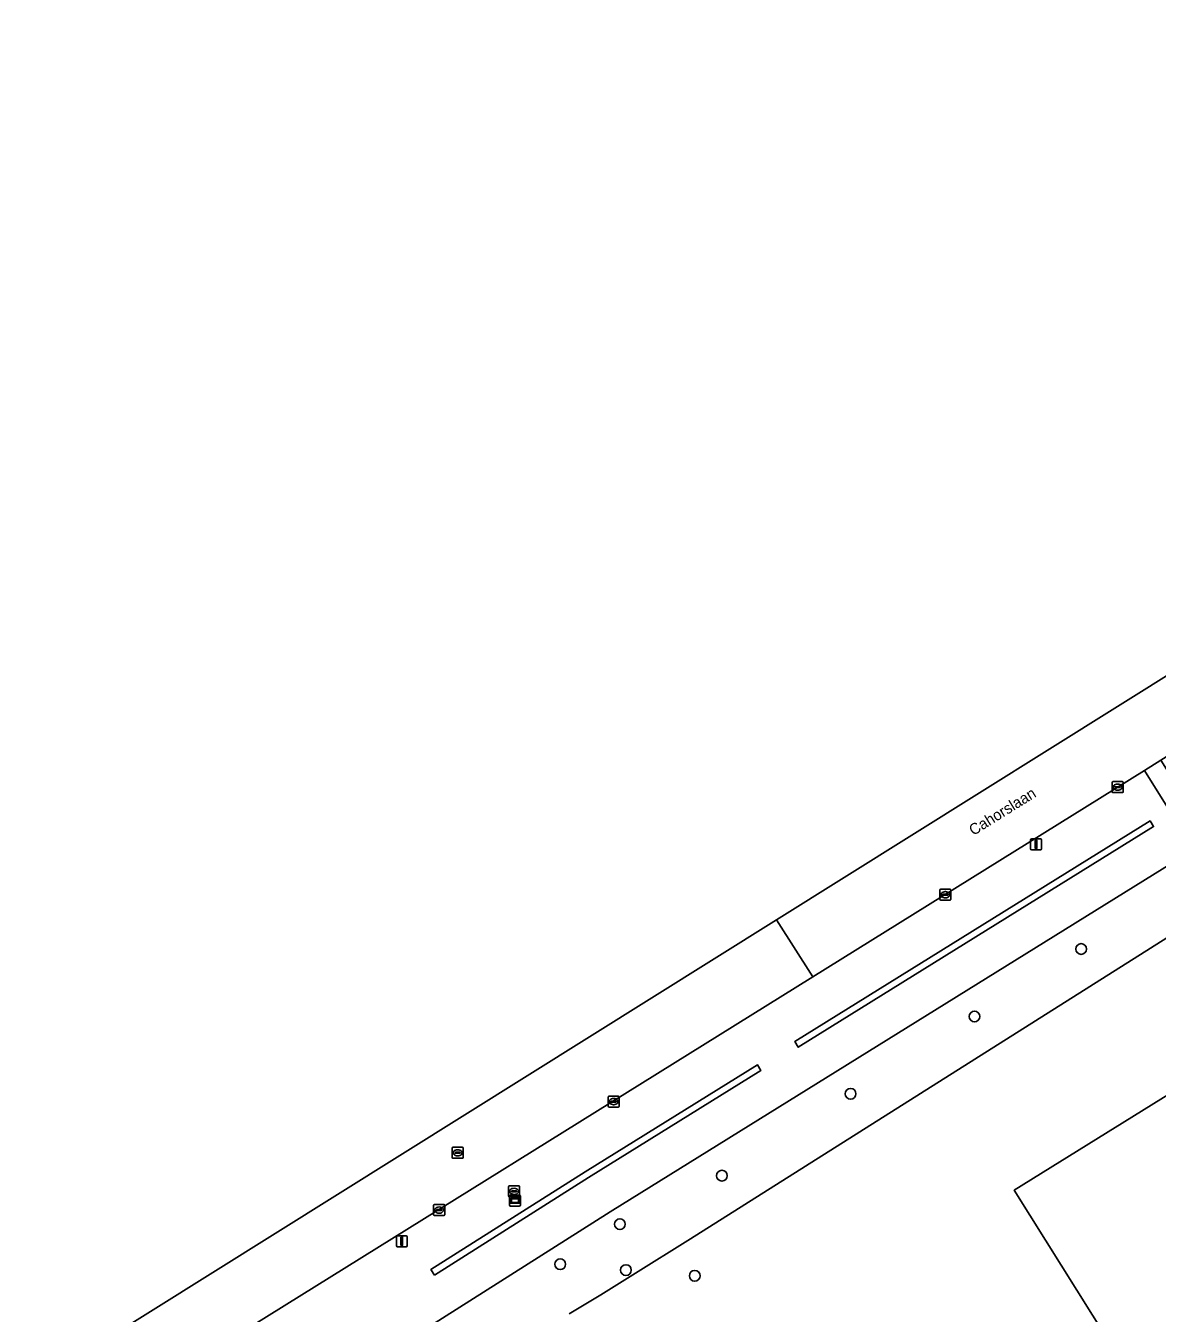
# Model space of a CAD drawing. Extents: x 158455 to 159797, y 387218 to 388672.
# Drawn here: x 158483.6 to 158586.4, y 387894.7 to 388011.6 of the extents above; entities that cross this region are included whole.
import ezdxf

# ---------------------------------------------------------------- set-up
doc = ezdxf.new("R2010")
doc.units = 0
for name, color, linetype in [('IMGEO_Boom', 7, 'Continuous'), ('IMGEO_Brandkraan', 7, 'Continuous'), ('IMGEO_Erf', 7, 'Continuous'), ('IMGEO_Groenvoorziening', 7, 'Continuous'), ('IMGEO_Haag', 7, 'Continuous'), ('IMGEO_Kolk', 7, 'Continuous'), ('IMGEO_Lichtmast', 7, 'Continuous'), ('IMGEO_Openbare_ruimte_label', 7, 'Continuous'), ('IMGEO_Pand', 7, 'Continuous'), ('IMGEO_Rijbaan_lokaal_gesloten', 7, 'Continuous'), ('IMGEO_Rijbaan_lokaal_open', 7, 'Continuous'), ('IMGEO_Rioolput', 7, 'Continuous'), ('IMGEO_Verklikker', 7, 'Continuous'), ('IMGEO_Voetpad_open', 7, 'Continuous')]:
    doc.layers.add(name, color=color, linetype=linetype)

msp = doc.modelspace()

# ---------------------------------------------------------------- linework, layer by layer
at = {"layer": 'IMGEO_Boom'}
for centre in [(158579.46, 387927.76), (158569.77, 387921.63), (158558.51, 387914.61), (158546.82, 387907.17), (158537.55, 387902.77), (158532.13, 387899.13), (158538.1, 387898.6), (158544.35, 387898.08)]:
    msp.add_circle(centre, 0.489, dxfattribs=at)
at = {"layer": 'IMGEO_Brandkraan'}
for p, q in [((158527.44, 387905.32), (158527.44, 387906.18)), ((158527.51, 387906.25), (158528.36, 387906.25)), ((158528.36, 387905.25), (158527.51, 387905.25)), ((158527.7, 387905.74), (158527.7, 387905.76)), ((158527.74, 387905.79), (158528.14, 387905.79)), ((158528.13, 387905.71), (158527.74, 387905.71)), ((158527.95, 387905.47), (158527.92, 387905.47)), ((158527.93, 387906.03), (158527.95, 387906.03)), ((158528.18, 387905.76), (158528.18, 387905.74)), ((158528.44, 387906.18), (158528.44, 387905.32))]:
    msp.add_line(p, q, dxfattribs=at)
for points in [[(158527.44, 387905.32), (158527.44, 387906.18)], [(158527.51, 387906.25), (158528.36, 387906.25)], [(158528.36, 387905.25), (158527.51, 387905.25)], [(158528.44, 387906.18), (158528.44, 387905.32)]]:
    msp.add_lwpolyline(points, dxfattribs=at)
for centre, radius, start, end in [((158527.51, 387906.18), 0.0765, 91.552, 178.448), ((158527.51, 387906.18), 0.0765, 91.552, 178.448), ((158527.51, 387905.33), 0.0765, 181.552, 268.448), ((158527.51, 387905.33), 0.0765, 181.552, 268.448), ((158527.74, 387905.75), 0.0403, 85.8775, 175.7526), ((158527.73, 387905.74), 0.0366, 178.938, 274.7102), ((158528.14, 387905.75), 0.043, 264.8664, 352.4533), ((158528.14, 387905.76), 0.0386, 1.7309, 96.639), ((158528.36, 387906.18), 0.0765, 1.552, 88.448), ((158528.36, 387906.18), 0.0765, 1.552, 88.448), ((158528.36, 387905.33), 0.0765, 271.552, 358.448), ((158528.36, 387905.33), 0.0765, 271.552, 358.448)]:
    msp.add_arc(centre, radius, start, end, dxfattribs=at)
for centre, major_axis, ratio, start_param, end_param in [((158527.92, 387905.75), (-0.387, 0.002), 0.722429, 4.712389, 7.853982), ((158527.95, 387905.75), (-0.39, 0.002), 0.717154, 1.570796, 4.712389)]:
    msp.add_ellipse(centre, major_axis=major_axis, ratio=ratio, start_param=start_param, end_param=end_param, dxfattribs=at)
at = {"layer": 'IMGEO_Erf'}
for points in [[(158573.38, 387905.85), (158595.86, 387919.82), (158595.79, 387919.92), (158598.08, 387921.36), (158594.51, 387926.76), (158593.7, 387926.26), (158592.36, 387928.36), (158590.22, 387926.79), (158588.61, 387928.98), (158590.79, 387930.57), (158590.71, 387930.96), (158543.97, 387901.44), (158538.73, 387898.18), (158535.83, 387896.34), (158532.94, 387894.61)], [(158570.32, 387880.74), (158572.79, 387877.35), (158575.89, 387872.44), (158584.05, 387859.54), (158587.13, 387854.66), (158588.43, 387852.56), (158594.08, 387856.34), (158584.31, 387871.94), (158591.71, 387876.58), (158573.38, 387905.85)]]:
    msp.add_lwpolyline(points, dxfattribs=at)
at = {"layer": 'IMGEO_Groenvoorziening'}
for points in [[(158488.57, 387883.89), (158493.31, 387876.39), (158500, 387880.63), (158536.68, 387903.89), (158589.7, 387936.8), (158585.21, 387943.98), (158555.08, 387925.23), (158500, 387890.96)], [(158553.75, 387918.84), (158553.44, 387919.35), (158585.72, 387939.39), (158586.04, 387938.88)], [(158585.72, 387939.39), (158553.44, 387919.35), (158553.75, 387918.84), (158586.04, 387938.88)], [(158520.7, 387898.14), (158520.38, 387898.65), (158534.4, 387907.53), (158550.04, 387917.24), (158550.36, 387916.73), (158534.71, 387907.02)], [(158520.7, 387898.14), (158534.71, 387907.02), (158550.36, 387916.73), (158550.04, 387917.24), (158534.4, 387907.53), (158520.38, 387898.65)]]:
    msp.add_lwpolyline(points, close=True, dxfattribs=at)
msp.add_lwpolyline([(158532.94, 387894.61), (158535.83, 387896.34), (158538.73, 387898.18), (158543.97, 387901.44), (158590.71, 387930.96), (158590.79, 387930.57), (158592.36, 387928.36), (158593.7, 387926.26), (158594.51, 387926.76), (158598.08, 387921.36), (158598.23, 387921.11), (158599.1, 387921.66), (158592.42, 387932.28), (158589.7, 387936.8), (158536.68, 387903.89), (158500, 387880.63)], dxfattribs=at)
at = {"layer": 'IMGEO_Haag'}
for points in [[(158585.72, 387939.39), (158553.44, 387919.35), (158553.75, 387918.84), (158586.04, 387938.88)], [(158520.7, 387898.14), (158534.71, 387907.02), (158550.36, 387916.73), (158550.04, 387917.24), (158534.4, 387907.53), (158520.38, 387898.65)]]:
    msp.add_lwpolyline(points, close=True, dxfattribs=at)
at = {"layer": 'IMGEO_Kolk'}
for p, q in [((158582.27, 387942.03), (158582.27, 387942.89)), ((158582.35, 387942.96), (158583.2, 387942.96)), ((158582.76, 387942.74), (158582.79, 387942.74)), ((158583.27, 387942.89), (158583.27, 387942.03)), ((158583.2, 387941.96), (158582.35, 387941.96)), ((158582.53, 387942.45), (158582.53, 387942.47)), ((158582.57, 387942.5), (158582.97, 387942.5)), ((158582.97, 387942.42), (158582.57, 387942.42)), ((158582.78, 387942.18), (158582.76, 387942.18)), ((158583.02, 387942.47), (158583.02, 387942.45)), ((158566.61, 387932.27), (158566.61, 387933.12)), ((158566.68, 387933.19), (158567.54, 387933.19)), ((158567.54, 387932.19), (158566.68, 387932.19)), ((158566.87, 387932.69), (158566.87, 387932.7)), ((158566.91, 387932.74), (158567.31, 387932.74)), ((158567.31, 387932.65), (158566.91, 387932.65)), ((158567.12, 387932.41), (158567.09, 387932.41)), ((158567.1, 387932.97), (158567.12, 387932.97)), ((158567.35, 387932.7), (158567.35, 387932.69)), ((158567.61, 387933.12), (158567.61, 387932.27)), ((158536.49, 387913.47), (158536.49, 387914.33)), ((158536.56, 387914.4), (158537.42, 387914.4)), ((158537.42, 387913.4), (158536.56, 387913.4)), ((158536.75, 387913.89), (158536.75, 387913.91)), ((158536.79, 387913.94), (158537.19, 387913.94)), ((158537.19, 387913.86), (158536.79, 387913.86)), ((158537, 387913.62), (158536.97, 387913.62)), ((158536.98, 387914.18), (158537, 387914.18)), ((158537.23, 387913.91), (158537.23, 387913.89)), ((158537.49, 387914.33), (158537.49, 387913.47)), ((158520.63, 387903.63), (158520.63, 387904.48)), ((158520.71, 387904.56), (158521.56, 387904.56)), ((158520.89, 387904.05), (158520.89, 387904.06)), ((158520.93, 387904.1), (158521.33, 387904.1)), ((158521.12, 387904.33), (158521.14, 387904.33)), ((158521.37, 387904.06), (158521.37, 387904.05)), ((158521.63, 387904.48), (158521.63, 387903.63)), ((158521.56, 387903.55), (158520.71, 387903.55)), ((158521.33, 387904.01), (158520.93, 387904.01)), ((158521.14, 387903.78), (158521.12, 387903.78))]:
    msp.add_line(p, q, dxfattribs=at)
for points in [[(158582.27, 387942.03), (158582.27, 387942.89)], [(158582.35, 387942.96), (158583.2, 387942.96)], [(158583.27, 387942.89), (158583.27, 387942.03)], [(158583.2, 387941.96), (158582.35, 387941.96)], [(158566.61, 387932.27), (158566.61, 387933.12)], [(158566.68, 387933.19), (158567.54, 387933.19)], [(158567.54, 387932.19), (158566.68, 387932.19)], [(158567.61, 387933.12), (158567.61, 387932.27)], [(158536.49, 387913.47), (158536.49, 387914.33)], [(158536.56, 387914.4), (158537.42, 387914.4)], [(158537.42, 387913.4), (158536.56, 387913.4)], [(158537.49, 387914.33), (158537.49, 387913.47)], [(158520.63, 387903.63), (158520.63, 387904.48)], [(158520.71, 387904.56), (158521.56, 387904.56)], [(158521.63, 387904.48), (158521.63, 387903.63)], [(158521.56, 387903.55), (158520.71, 387903.55)]]:
    msp.add_lwpolyline(points, dxfattribs=at)
for centre, radius, start, end in [((158582.35, 387942.88), 0.0765, 91.552, 178.448), ((158582.35, 387942.88), 0.0765, 91.552, 178.448), ((158583.2, 387942.88), 0.0765, 1.552, 88.448), ((158583.2, 387942.88), 0.0765, 1.552, 88.448), ((158582.35, 387942.04), 0.0765, 181.552, 268.448), ((158582.35, 387942.04), 0.0765, 181.552, 268.448), ((158582.57, 387942.46), 0.0403, 85.8775, 175.7526), ((158582.57, 387942.45), 0.0366, 178.938, 274.7102), ((158582.98, 387942.46), 0.0386, 1.7309, 96.639), ((158582.97, 387942.46), 0.043, 264.8664, 352.4533), ((158583.2, 387942.04), 0.0765, 271.552, 358.448), ((158583.2, 387942.04), 0.0765, 271.552, 358.448), ((158566.69, 387933.12), 0.0765, 91.552, 178.448), ((158566.69, 387933.12), 0.0765, 91.552, 178.448), ((158566.69, 387932.27), 0.0765, 181.552, 268.448), ((158566.69, 387932.27), 0.0765, 181.552, 268.448), ((158566.91, 387932.7), 0.0403, 85.8775, 175.7526), ((158566.9, 387932.69), 0.0366, 178.938, 274.7102), ((158567.31, 387932.7), 0.0386, 1.7309, 96.639), ((158567.31, 387932.69), 0.043, 264.8664, 352.4533), ((158567.53, 387933.12), 0.0765, 1.552, 88.448), ((158567.53, 387933.12), 0.0765, 1.552, 88.448), ((158567.53, 387932.27), 0.0765, 271.552, 358.448), ((158567.53, 387932.27), 0.0765, 271.552, 358.448), ((158536.57, 387914.32), 0.0765, 91.552, 178.448), ((158536.57, 387914.32), 0.0765, 91.552, 178.448), ((158536.57, 387913.48), 0.0765, 181.552, 268.448), ((158536.57, 387913.48), 0.0765, 181.552, 268.448), ((158536.79, 387913.9), 0.0403, 85.8775, 175.7526), ((158536.78, 387913.89), 0.0366, 178.938, 274.7102), ((158537.19, 387913.9), 0.0386, 1.7309, 96.639), ((158537.19, 387913.9), 0.043, 264.8664, 352.4533), ((158537.41, 387914.32), 0.0765, 1.552, 88.448), ((158537.41, 387914.32), 0.0765, 1.552, 88.448), ((158537.41, 387913.48), 0.0765, 271.552, 358.448), ((158537.41, 387913.48), 0.0765, 271.552, 358.448), ((158520.71, 387904.48), 0.0765, 91.552, 178.448), ((158520.71, 387904.48), 0.0765, 91.552, 178.448), ((158520.93, 387904.06), 0.0403, 85.8775, 175.7526), ((158520.93, 387904.05), 0.0366, 178.938, 274.7102), ((158521.34, 387904.06), 0.0386, 1.7309, 96.639), ((158521.33, 387904.05), 0.043, 264.8664, 352.4533), ((158521.56, 387904.48), 0.0765, 1.552, 88.448), ((158521.56, 387904.48), 0.0765, 1.552, 88.448), ((158520.71, 387903.63), 0.0765, 181.552, 268.448), ((158520.71, 387903.63), 0.0765, 181.552, 268.448), ((158521.56, 387903.63), 0.0765, 271.552, 358.448), ((158521.56, 387903.63), 0.0765, 271.552, 358.448)]:
    msp.add_arc(centre, radius, start, end, dxfattribs=at)
for centre, major_axis, ratio, start_param, end_param in [((158582.76, 387942.46), (-0.387, 0.002), 0.722429, 4.712389, 7.853982), ((158582.78, 387942.46), (-0.39, 0.002), 0.717154, 1.570796, 4.712389), ((158567.1, 387932.69), (-0.387, 0.002), 0.722429, 4.712389, 7.853982), ((158567.12, 387932.69), (-0.39, 0.002), 0.717154, 1.570796, 4.712389), ((158536.98, 387913.9), (-0.387, 0.002), 0.722429, 4.712389, 7.853982), ((158537, 387913.9), (-0.39, 0.002), 0.717154, 1.570796, 4.712389), ((158521.12, 387904.05), (-0.387, 0.002), 0.722429, 4.712389, 7.853982), ((158521.14, 387904.05), (-0.39, 0.002), 0.717154, 1.570796, 4.712389)]:
    msp.add_ellipse(centre, major_axis=major_axis, ratio=ratio, start_param=start_param, end_param=end_param, dxfattribs=at)
at = {"layer": 'IMGEO_Lichtmast'}
for p, q in [((158574.87, 387936.86), (158574.87, 387937.66)), ((158574.87, 387937.66), (158574.87, 387936.86)), ((158574.97, 387937.76), (158575.76, 387937.76)), ((158575.76, 387937.76), (158574.97, 387937.76)), ((158575.86, 387937.66), (158575.86, 387936.86)), ((158575.86, 387936.86), (158575.86, 387937.66)), ((158575.76, 387936.76), (158574.97, 387936.76)), ((158574.97, 387936.76), (158575.76, 387936.76)), ((158517.34, 387901.72), (158518.13, 387901.72)), ((158518.13, 387901.72), (158517.34, 387901.72)), ((158517.24, 387900.82), (158517.24, 387901.62)), ((158517.24, 387901.62), (158517.24, 387900.82)), ((158518.13, 387900.72), (158517.34, 387900.72)), ((158517.34, 387900.72), (158518.13, 387900.72)), ((158518.23, 387901.62), (158518.23, 387900.82)), ((158518.23, 387900.82), (158518.23, 387901.62))]:
    msp.add_line(p, q, dxfattribs=at)
for points in [[(158575.29, 387937.64), (158575.44, 387937.64), (158575.44, 387936.89), (158575.29, 387936.89), (158575.29, 387937.64)], [(158517.66, 387901.6), (158517.81, 387901.6), (158517.81, 387900.85), (158517.66, 387900.85), (158517.66, 387901.6)]]:
    msp.add_lwpolyline(points, dxfattribs=at)
for centre, start, end in [((158574.97, 387937.66), 90, 180), ((158574.97, 387937.66), 90, 180), ((158574.97, 387936.86), 180, 270), ((158574.97, 387936.86), 180, 270), ((158575.76, 387937.66), 0, 90), ((158575.76, 387937.66), 360, 90), ((158575.76, 387936.86), 270, 0), ((158575.76, 387936.86), 270, 0), ((158517.34, 387901.62), 90, 180), ((158517.34, 387901.62), 90, 180), ((158518.13, 387901.62), 0, 90), ((158518.13, 387901.62), 360, 90), ((158517.34, 387900.82), 180, 270), ((158517.34, 387900.82), 180, 270), ((158518.13, 387900.82), 270, 0), ((158518.13, 387900.82), 270, 0)]:
    msp.add_arc(centre, 0.1, start, end, dxfattribs=at)
at = {"layer": 'IMGEO_Pand'}
msp.add_lwpolyline([(158616.01, 387892.68), (158601.25, 387916.29), (158598.23, 387921.11), (158598.08, 387921.36), (158595.79, 387919.92), (158595.86, 387919.82), (158573.38, 387905.85), (158591.71, 387876.58), (158584.31, 387871.94), (158594.08, 387856.34), (158588.43, 387852.56), (158595.41, 387841.18), (158600.94, 387832.3), (158601.13, 387832.42), (158628.2, 387849.45), (158625.53, 387853.67), (158636.27, 387860.47), (158626.49, 387876), (158626.21, 387876.45), (158618.06, 387871.33), (158607.88, 387887.6), (158615.92, 387892.63)], close=True, dxfattribs=at)
at = {"layer": 'IMGEO_Rijbaan_lokaal_gesloten'}
msp.add_lwpolyline([(158551.78, 387930.42), (158555.08, 387925.23), (158585.21, 387943.98), (158586.7, 387944.91), (158674.85, 388000), (158679.8, 388003.1), (158680.44, 388003.51), (158681.26, 388004.02), (158683.4, 388005.33), (158684.98, 388006.32), (158684.9, 388006.43), (158681.62, 388011.61), (158681.62, 388011.61)], close=True, dxfattribs=at)
at = {"layer": 'IMGEO_Rijbaan_lokaal_open'}
msp.add_lwpolyline([(158486.08, 387882.44), (158486.08, 387882.44), (158486.1, 387882.45), (158486.56, 387882.59), (158486.83, 387882.71), (158488.57, 387883.89), (158500, 387890.96), (158555.08, 387925.23), (158551.78, 387930.42), (158483.57, 387887.76)], close=True, dxfattribs=at)
at = {"layer": 'IMGEO_Rioolput'}
for p, q in [((158522.31, 387908.83), (158522.31, 387909.68)), ((158522.38, 387909.75), (158523.24, 387909.75)), ((158523.24, 387908.75), (158522.38, 387908.75)), ((158522.57, 387909.25), (158522.57, 387909.26)), ((158522.61, 387909.3), (158523.01, 387909.3)), ((158523.01, 387909.21), (158522.61, 387909.21)), ((158522.82, 387908.97), (158522.79, 387908.97)), ((158522.8, 387909.53), (158522.82, 387909.53)), ((158523.05, 387909.26), (158523.05, 387909.25)), ((158523.31, 387909.68), (158523.31, 387908.83))]:
    msp.add_line(p, q, dxfattribs=at)
for points in [[(158522.31, 387908.83), (158522.31, 387909.68)], [(158522.38, 387909.75), (158523.24, 387909.75)], [(158523.24, 387908.75), (158522.38, 387908.75)], [(158523.31, 387909.68), (158523.31, 387908.83)]]:
    msp.add_lwpolyline(points, dxfattribs=at)
for centre, radius, start, end in [((158522.39, 387909.68), 0.0765, 91.552, 178.448), ((158522.39, 387909.68), 0.0765, 91.552, 178.448), ((158522.39, 387908.83), 0.0765, 181.552, 268.448), ((158522.39, 387908.83), 0.0765, 181.552, 268.448), ((158522.61, 387909.26), 0.0403, 85.8775, 175.7526), ((158522.6, 387909.25), 0.0366, 178.938, 274.7102), ((158523.01, 387909.26), 0.0386, 1.7309, 96.639), ((158523.01, 387909.25), 0.043, 264.8664, 352.4533), ((158523.23, 387909.68), 0.0765, 1.552, 88.448), ((158523.23, 387909.68), 0.0765, 1.552, 88.448), ((158523.23, 387908.83), 0.0765, 271.552, 358.448), ((158523.23, 387908.83), 0.0765, 271.552, 358.448)]:
    msp.add_arc(centre, radius, start, end, dxfattribs=at)
for centre, major_axis, ratio, start_param, end_param in [((158522.8, 387909.25), (-0.387, 0.002), 0.722429, 4.712389, 7.853982), ((158522.82, 387909.25), (-0.39, 0.002), 0.717154, 1.570796, 4.712389)]:
    msp.add_ellipse(centre, major_axis=major_axis, ratio=ratio, start_param=start_param, end_param=end_param, dxfattribs=at)
at = {"layer": 'IMGEO_Verklikker'}
for p, q in [((158527.52, 387904.51), (158527.52, 387905.31)), ((158527.52, 387905.31), (158527.52, 387904.51)), ((158527.62, 387905.41), (158528.41, 387905.41)), ((158528.41, 387905.41), (158527.62, 387905.41)), ((158528.51, 387905.31), (158528.51, 387904.51)), ((158528.51, 387904.51), (158528.51, 387905.31)), ((158528.41, 387904.41), (158527.62, 387904.41)), ((158527.62, 387904.41), (158528.41, 387904.41))]:
    msp.add_line(p, q, dxfattribs=at)
for points in [[(158527.63, 387905.14), (158528.41, 387905.14), (158528.41, 387904.67), (158527.63, 387904.67), (158527.63, 387905.14)], [(158527.69, 387905.07), (158527.69, 387904.74), (158528.35, 387904.74), (158528.35, 387905.07), (158527.69, 387905.07)]]:
    msp.add_lwpolyline(points, dxfattribs=at)
for centre, start, end in [((158527.62, 387905.31), 90, 180), ((158527.62, 387905.31), 90, 180), ((158528.41, 387905.31), 0, 90), ((158528.41, 387905.31), 360, 90), ((158527.62, 387904.51), 180, 270), ((158527.62, 387904.51), 180, 270), ((158528.41, 387904.51), 270, 0), ((158528.41, 387904.51), 270, 0)]:
    msp.add_arc(centre, 0.1, start, end, dxfattribs=at)
at = {"layer": 'IMGEO_Voetpad_open'}
msp.add_lwpolyline([(158600.33, 387923.19), (158595.51, 387930.78), (158591.01, 387938.08), (158586.7, 387944.91), (158585.21, 387943.98), (158589.7, 387936.8), (158592.42, 387932.28), (158599.1, 387921.66), (158598.23, 387921.11), (158601.25, 387916.29), (158616.01, 387892.68), (158615.92, 387892.63), (158616.21, 387892.22), (158617.14, 387892.85), (158607.58, 387907.94), (158607.51, 387908.4), (158607.96, 387910.5), (158607.97, 387911)], dxfattribs=at)

# ---------------------------------------------------------------- texts
at = {"layer": 'IMGEO_Openbare_ruimte_label'}
msp.add_text('Cahorslaan', height=1, rotation=31.9568, dxfattribs=at).set_placement((158569.66, 387938.02))

doc.saveas('drawing.dxf')
